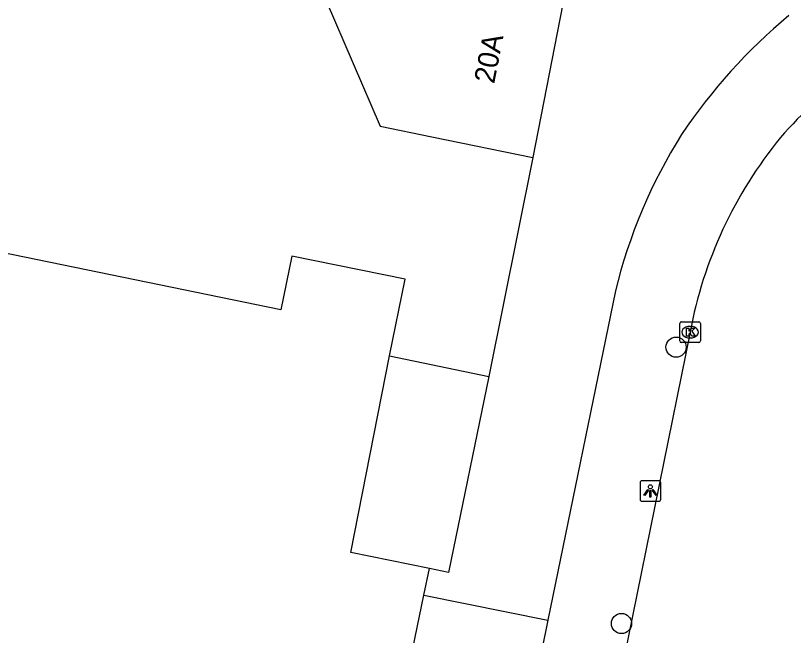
# Model space of a CAD drawing. Extents: x 158087 to 159494, y 382905 to 383981.
# Drawn here: x 158768.84 to 158806.52, y 383045.4 to 383075.44 of the extents above; entities that cross this region are included whole.
import ezdxf

# ---------------------------------------------------------------- set-up
doc = ezdxf.new("R2010")
doc.units = 0
for name, color, linetype in [('IMGEO_Boom', 7, 'Continuous'), ('IMGEO_Kolk', 7, 'Continuous'), ('IMGEO_Lichtpunt', 7, 'Continuous'), ('IMGEO_Pand', 7, 'Continuous'), ('IMGEO_Pand_nummerreeks', 7, 'Continuous'), ('IMGEO_Parkeervlak_open', 7, 'Continuous'), ('IMGEO_Rijbaan_lokaal_open', 7, 'Continuous'), ('IMGEO_Voetpad_open', 7, 'Continuous')]:
    doc.layers.add(name, color=color, linetype=linetype)

msp = doc.modelspace()

# ---------------------------------------------------------------- linework, layer by layer
at = {"layer": 'IMGEO_Boom'}
for centre in [(158800.831, 383059.368), (158798.187, 383045.98)]:
    msp.add_circle(centre, 0.489, dxfattribs=at)
at = {"layer": 'IMGEO_Kolk'}
for p, q in [((158801.009, 383059.67), (158801.009, 383060.522)), ((158801.084, 383060.596), (158801.936, 383060.596)), ((158802.01, 383060.522), (158802.01, 383059.67)), ((158801.497, 383060.376), (158801.522, 383060.376)), ((158801.52, 383059.816), (158801.495, 383059.816)), ((158801.936, 383059.596), (158801.084, 383059.596))]:
    msp.add_line(p, q, dxfattribs=at)
for points in [[(158801.009, 383059.67), (158801.009, 383060.522)], [(158801.084, 383060.596), (158801.936, 383060.596)], [(158802.01, 383060.522), (158802.01, 383059.67)], [(158801.33, 383060.296), (158801.453, 383060.296), (158801.453, 383060.145), (158801.583, 383060.296), (158801.747, 383060.296), (158801.601, 383060.145), (158801.754, 383059.896), (158801.602, 383059.896), (158801.517, 383060.06), (158801.453, 383059.993), (158801.453, 383059.896), (158801.33, 383059.896), (158801.33, 383060.296)], [(158801.936, 383059.596), (158801.084, 383059.596)]]:
    msp.add_lwpolyline(points, dxfattribs=at)
for centre, start, end in [((158801.086, 383060.52), 91.552, 178.448), ((158801.086, 383060.52), 91.552, 178.448), ((158801.934, 383060.52), 1.552, 88.448), ((158801.934, 383060.52), 1.552, 88.448), ((158801.086, 383059.672), 181.552, 268.448), ((158801.086, 383059.672), 181.552, 268.448), ((158801.934, 383059.672), 271.552, 358.448), ((158801.934, 383059.672), 271.552, 358.448)]:
    msp.add_arc(centre, 0.0765, start, end, dxfattribs=at)
for centre, major_axis, ratio, start_param, end_param in [((158801.496, 383060.096), (-0.387, 0.002), 0.722429, 4.712389, 7.853982), ((158801.521, 383060.096), (-0.39, 0.002), 0.717154, 1.570796, 4.712389)]:
    msp.add_ellipse(centre, major_axis=major_axis, ratio=ratio, start_param=start_param, end_param=end_param, dxfattribs=at)
at = {"layer": 'IMGEO_Lichtpunt'}
for p, q in [((158799.09, 383052.804), (158799.09, 383051.997)), ((158799.09, 383052.804), (158799.09, 383051.997)), ((158799.992, 383052.899), (158799.184, 383052.899)), ((158799.992, 383052.899), (158799.184, 383052.899)), ((158800.086, 383051.997), (158800.086, 383052.804)), ((158800.086, 383051.997), (158800.086, 383052.804)), ((158799.184, 383051.903), (158799.992, 383051.903)), ((158799.184, 383051.903), (158799.992, 383051.903))]:
    msp.add_line(p, q, dxfattribs=at)
for points in [[(158799.464, 383052.468), (158799.503, 383052.44), (158799.315, 383052.178), (158799.277, 383052.205), (158799.464, 383052.468)], [(158799.566, 383052.42), (158799.613, 383052.42), (158799.613, 383052.098), (158799.566, 383052.098), (158799.566, 383052.42)], [(158799.676, 383052.44), (158799.714, 383052.467), (158799.901, 383052.205), (158799.862, 383052.177), (158799.676, 383052.44)]]:
    msp.add_lwpolyline(points, dxfattribs=at)
msp.add_circle((158799.589, 383052.602), 0.0994, dxfattribs=at)
for centre, start, end in [((158799.184, 383052.804), 90, 180), ((158799.184, 383052.804), 90, 180), ((158799.992, 383052.804), 0, 90), ((158799.992, 383052.804), 0, 90), ((158799.184, 383051.997), 180, 270), ((158799.184, 383051.997), 180, 270), ((158799.992, 383051.997), 270, 0), ((158799.992, 383051.997), 270, 360)]:
    msp.add_arc(centre, 0.0946, start, end, dxfattribs=at)
at = {"layer": 'IMGEO_Pand'}
for points in [[(158776.04, 383094.375), (158786.505, 383070.079), (158789.002, 383069.567), (158793.9, 383068.563)], [(158795.608, 383077.34), (158793.9, 383068.563)], [(158786.952, 383058.944), (158787.714, 383062.657), (158782.229, 383063.783), (158781.694, 383061.178), (158748.125, 383068.073), (158746.016, 383057.807)], [(158788.884, 383048.644), (158785.074, 383049.427), (158786.952, 383058.944)], [(158786.952, 383058.944), (158791.767, 383057.954)], [(158791.767, 383057.954), (158789.816, 383048.453), (158788.884, 383048.644)], [(158788.619, 383047.357), (158788.884, 383048.644)], [(158784.337, 383021.381), (158783.308, 383021.593), (158788.619, 383047.357)]]:
    msp.add_lwpolyline(points, dxfattribs=at)
at = {"layer": 'IMGEO_Parkeervlak_open'}
msp.add_lwpolyline([(158793.9, 383068.563), (158791.767, 383057.954)], dxfattribs=at)
at = {"layer": 'IMGEO_Rijbaan_lokaal_open'}
msp.add_lwpolyline([(158801.51, 383060.092), (158798.504, 383045.305), (158796.167, 383033.685), (158793.719, 383021.9), (158793.205, 383018.967), (158792.953, 383017.671)], dxfattribs=at)
for centre, radius, start, end in [((158821.836, 383055.818), 21.026, 113.0707, 139.3202), ((158822.036, 383056.29), 20.875, 140.6609, 169.5063)]:
    msp.add_arc(centre, radius, start, end, dxfattribs=at)
at = {"layer": 'IMGEO_Voetpad_open'}
for points in [[(158797.897, 383062.091), (158794.614, 383046.144)], [(158788.619, 383047.357), (158794.614, 383046.144)], [(158794.614, 383046.144), (158789.4, 383020.358)]]:
    msp.add_lwpolyline(points, dxfattribs=at)
for centre, radius, start, end in [((158824.024, 383054.249), 27.633, 129.9378, 146.057), ((158822.818, 383056.04), 25.645, 147.8724, 166.3516)]:
    msp.add_arc(centre, radius, start, end, dxfattribs=at)

# ---------------------------------------------------------------- texts
at = {"layer": 'IMGEO_Pand_nummerreeks'}
msp.add_text('20A', height=1, rotation=78.9879, dxfattribs=at).set_placement((158792.021, 383072.101))

doc.saveas('drawing.dxf')
